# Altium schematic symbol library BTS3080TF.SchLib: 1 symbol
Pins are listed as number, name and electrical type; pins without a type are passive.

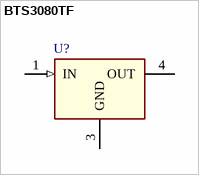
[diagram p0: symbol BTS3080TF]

## BTS3080TF
designator U?  (value not drawn)
HITFET Smart Low-Side Power Switch, VIN 5.5V, IL 3A; Manufacturer: Infineon Technologies
footprint TO228P998X250-3N-V1
footprint TO228P998X250-3N-1
pins: 1 IN (in) "Input Pin", 3 GND (power) "Ground,Source For Power DMOS", 4 OUT (power) "Drain,Load Connection For Power DMOS"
